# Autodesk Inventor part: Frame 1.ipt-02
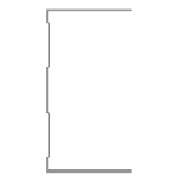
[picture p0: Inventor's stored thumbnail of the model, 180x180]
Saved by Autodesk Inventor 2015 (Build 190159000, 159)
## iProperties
IsCustomPart: 1
Created: 2015-04
Part Number: Frame 1.ipt-02
Material: Aluminum 6061
Description: Kévin Novo
Document SubType Name: Modeling
Standard: Kevin
Designer: suporte
Standards Organization: Kevin
Language: en-US
Size Designation: (Unnamed 2)
Categories: <MemberInstance><Categories><Category DisplayName="Structural Shapes" InternalName="089c4875-fa83-4c05-b084-43b9cc11f5ed" Mnemonic="GRDR"><CategoryParameter Dis
Density: 2.7 g/cm^3
Appearance: Aluminum - Flat
_CCFamilyMember: 2
_CCFamilyDisplayName: Kévin - Kévin Novo
_FrameMemberDoc: Frame Member File
_Version: 15.0.0
_GetPNFromCC: 1
G_W: 50,000 mm
G_H: 75,000 mm
G_L: 2100,000 mm
+834F0B77-849A-4745-B9E2-197B072F7595+CUTDETAIL1: Notch
+F0F93DD6-A83B-4B83-A87D-84D9C4C0E5E9+CUTDETAIL2: Notch
Author: suporte
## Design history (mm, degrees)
node "Start Plane"
node "End Plane"
sketch "Sketch"
  geometry: L1 (24.7, 37.5)-(24.7, 36.9); L2 (24.7, 36.9)-(-24.7, 36.9); L3 (-24.7, -36.9)-(24.7, -36.9); L4 (24.7, -36.9)-(24.7, -37.5); L5 (24.7, -37.5)-(-25.3, -37.5); L6 (-25.3, 37.5)-(24.7, 37.5); L7 (-24.7, 36.9)-(-24.7, 31.9); L8 (-24.7, 31.9)-(-23.3, 30.5); L9 (-23.3, 30.5)-(-23.3, 10.934); L10 (-23.3, 10.934)-(-24.7, 9.534); L11 (-24.7, 9.534)-(-24.7, -9.534); L12 (-24.7, -9.534)-(-23.3, -10.934); L13 (-23.3, -10.934)-(-23.3, -30.5); L14 (-23.3, -30.5)-(-24.7, -31.9); L15 (-24.7, -31.9)-(-24.7, -36.9); L16 (-25.3, -37.5)-(-25.3, -31.651); L17 (-25.3, -31.651)-(-23.9, -30.251); L18 (-23.9, -30.251)-(-23.9, -11.183); L19 (-23.9, -11.183)-(-25.3, -9.783); L20 (-25.3, -9.783)-(-25.3, 9.783); L21 (-25.3, 9.783)-(-23.9, 11.183); L22 (-23.9, 11.183)-(-23.9, 30.251); L23 (-23.9, 30.251)-(-25.3, 31.651); L24 (-25.3, 31.651)-(-25.3, 37.5); L25 (-25.3, 0)-(30.37, 0); 3 further points
  constraints: 50 end point, 10 point on line, 9 parallel, 5 perpendicular, 4 equal length, 3 midpoint, 3 vertical, 2 vertical alignment, 1 collinear, 1 horizontal, 1 horizontal alignment
  dimensions: "d3" = 0.6 distance of L1.start L1.end (= d6); "d5" = 75 distance between parallel lines of L5 L6; "d6" = 0.6 distance between parallel lines of L24 L7 (= d8); "d7" = 0.6 distance between parallel lines of L8 L23 (= d8); "d8" = 0.6 distance between parallel lines of L22 L9 (= d12); "Espessura" = 0.6 distance between parallel lines of L17 L14; "d10" = 0.6 distance between parallel lines of L13 L18 (= Espessura); "d11" = 0.6 distance between parallel lines of L12 L19 (= Espessura); "d12" = 0.6 distance between parallel lines of L21 L10 (= d11); "d13" = 5 distance of L2.end L7.end; "d15" = 135 deg angle of L9 L8; "d16" = 2 distance between parallel lines of L24 L9; "d17" = 50 distance of L6.start L1.start
extrude "Body" join sketch "Sketch" stored distance "d24" = 0.13; taper "d25" = 0 deg
node "Driven Length"
  sketch "Sketch10"
    geometry: L1 (0, 0)-(10, 0) reference
    constraints: 2 end point, 1 horizontal
  workplane "Work Plane7"
  sketch "Sketch11"
    geometry: L1 (-2, 0)-(12, 0) reference; L2 (-2, 2100)-(12, 2100) reference
    dimensions: "d27" = 2100 distance between parallel lines of L1 L2 (derived)
workplane "Work Plane8"
workplane "Work Plane9"
workplane "Work Plane10"
sketch "Sketch12"
  geometry: L1 (24.7, 37.5)-(24.7, 36.9); L2 (24.7, 36.9)-(-24.7, 36.9); L3 (-24.7, 36.9)-(-24.7, 31.9); L4 (-24.7, 31.9)-(-23.3, 30.5); L5 (-23.3, 30.5)-(-23.3, 10.934); L6 (-23.3, 10.934)-(-24.7, 9.534); L7 (-24.7, 9.534)-(-24.7, -9.534); L8 (-24.7, -9.534)-(-23.3, -10.934); L9 (-23.3, -10.934)-(-23.3, -30.5); L10 (-23.3, -30.5)-(-24.7, -31.9); L11 (-24.7, -31.9)-(-24.7, -36.9); L12 (-24.7, -36.9)-(24.7, -36.9); L13 (24.7, -36.9)-(24.7, -37.5); L14 (24.7, -37.5)-(-25.3, -37.5); L15 (-25.3, -37.5)-(-25.3, -31.651); L16 (-25.3, -31.651)-(-23.9, -30.251); L17 (-23.9, -30.251)-(-23.9, -11.183); L18 (-23.9, -11.183)-(-25.3, -9.783); L19 (-25.3, -9.783)-(-25.3, 9.783); L20 (-25.3, 9.783)-(-23.9, 11.183); L21 (-23.9, 11.183)-(-23.9, 30.251); L22 (-23.9, 30.251)-(-25.3, 31.651); L23 (-25.3, 31.651)-(-25.3, 37.5); L24 (-25.3, 37.5)-(24.7, 37.5)
  constraints: 48 end point, 10 point on line
extrude "Extrusion3" cut sketch "Sketch12" stored distance "d36" = 0.13; taper "d37" = 0 deg
workplane "Work Plane11"
workplane "Work Plane12"
workplane "Work Plane13"
sketch "Sketch13"
  geometry: L1 (24.7, 37.5)-(24.7, 36.9); L2 (24.7, 36.9)-(-24.7, 36.9); L3 (-24.7, 36.9)-(-24.7, 31.9); L4 (-24.7, 31.9)-(-23.3, 30.5); L5 (-23.3, 30.5)-(-23.3, 10.934); L6 (-23.3, 10.934)-(-24.7, 9.534); L7 (-24.7, 9.534)-(-24.7, -9.534); L8 (-24.7, -9.534)-(-23.3, -10.934); L9 (-23.3, -10.934)-(-23.3, -30.5); L10 (-23.3, -30.5)-(-24.7, -31.9); L11 (-24.7, -31.9)-(-24.7, -36.9); L12 (-24.7, -36.9)-(24.7, -36.9); L13 (24.7, -36.9)-(24.7, -37.5); L14 (24.7, -37.5)-(-25.3, -37.5); L15 (-25.3, -37.5)-(-25.3, -31.651); L16 (-25.3, -31.651)-(-23.9, -30.251); L17 (-23.9, -30.251)-(-23.9, -11.183); L18 (-23.9, -11.183)-(-25.3, -9.783); L19 (-25.3, -9.783)-(-25.3, 9.783); L20 (-25.3, 9.783)-(-23.9, 11.183); L21 (-23.9, 11.183)-(-23.9, 30.251); L22 (-23.9, 30.251)-(-25.3, 31.651); L23 (-25.3, 31.651)-(-25.3, 37.5); L24 (-25.3, 37.5)-(24.7, 37.5)
  constraints: 48 end point, 10 point on line
extrude "Extrusion4" cut sketch "Sketch13" stored distance "d38" = 0.13; taper "d39" = 0 deg
body "Solid1"
other parameters: "G_OFFSET_START" = 0 [user parameter; used in 1 equation term], "G_OFFSET_END" = 0 [user parameter; used in 1 equation term], "d22" = 0 (computed from G_OFFSET_START), "G_L" = 2100 (= d27) [user parameter], "d34" = 90 deg
